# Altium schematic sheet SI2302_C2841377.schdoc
size 127 x 101 mm
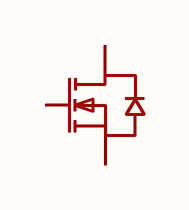
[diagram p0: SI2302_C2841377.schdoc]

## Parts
Q?  si2302  [SOT-23-3_L2.9-W1.3-P1.90-LS2.4-BR]  (value not drawn)

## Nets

Not connected (* = marked no-connect by the designer): Q? 1(G) 2(S) 3(D)

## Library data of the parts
Q? = si2302: 数量:1个N沟道;漏源电压(Vdss):20V;连续漏极电流(Id):2.6A;导通电阻(RDS(on)):120mΩ@2.5V;耗散功率(Pd):900mW;阈值电压(Vgs(th)):1.5V;; Manufacturer: TECH PUBLIC(台舟); Symbol: SI2302_C2841377; AddInBom: yes; ModelId: c62791f0466c4ae2a892c056b845b0ca; ModelName: SOT-23-3P_L2.9-W1.3-H1.0-LS2.4-P0.95; ModelTransform: 98.425,114.173,0,180,0,0,0.0005,-0.0005,0; Number: 1个N沟道; Drain to Source Voltage: 20V; Current - Continuous Drain(Id): 2.6A; Pd - Power Dissipation: 900mW; Gate Threshold Voltage (Vgs(th)): 1.5V; Input Capacitance(Ciss): 880pF; Type: N沟道; Output Capacitance(Coss): 270pF; Vgs: ±8V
